// Mitsubishi GX Works2 project: DEMO_CCLv2-GATEWAY-V6ENET   PLC: L26-BT
// Demo V6 comm with CC-Link through HMS gateway

PROGRAM MAIN
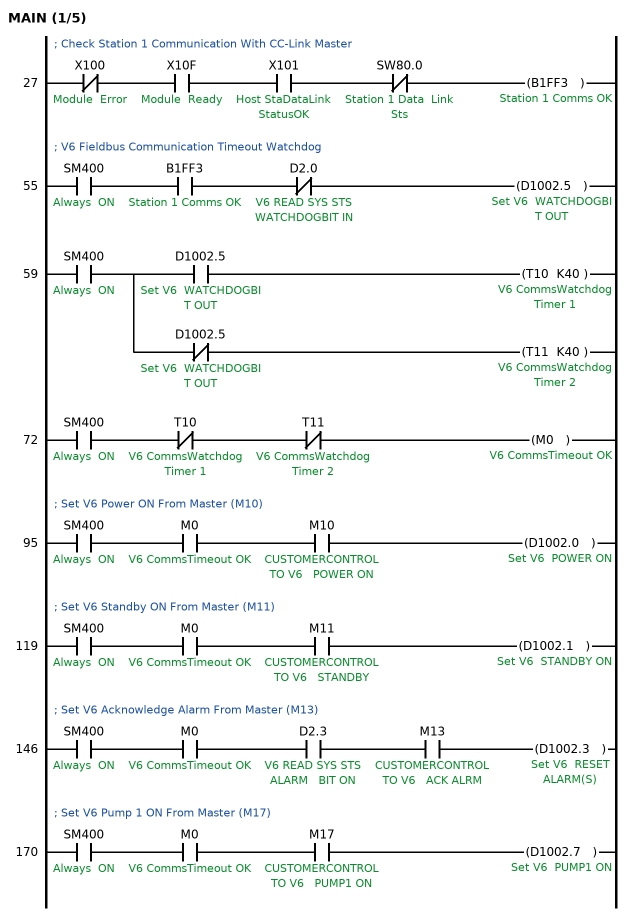
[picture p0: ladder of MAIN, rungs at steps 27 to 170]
; Check Station 1 Communication With CC-Link Master
27    LDI     X100  ; Module  Error
      AND     X10F  ; Module  Ready
      AND     X101  ; Host StaDataLinkStatusOK
      ANI     SW80.0  ; Station 1 Data  Link Sts
      OUT     B1FF3  ; Station 1 Comms OK
; V6 Fieldbus Communication Timeout Watchdog
55    LD      SM400  ; Always  ON
      AND     B1FF3  ; Station 1 Comms OK
      ANI     D2.0  ; V6 READ SYS STS WATCHDOGBIT IN
      OUT     D1002.5  ; Set V6  WATCHDOGBIT OUT
59    LD      SM400  ; Always  ON
      MPS
      AND     D1002.5  ; Set V6  WATCHDOGBIT OUT
      OUT     T10 K40  ; V6 CommsWatchdogTimer 1
      MPP
      ANI     D1002.5  ; Set V6  WATCHDOGBIT OUT
      OUT     T11 K40  ; V6 CommsWatchdogTimer 2
72    LD      SM400  ; Always  ON
      ANI     T10  ; V6 CommsWatchdogTimer 1
      ANI     T11  ; V6 CommsWatchdogTimer 2
      OUT     M0  ; V6 CommsTimeout OK
; Set V6 Power ON From Master (M10)
95    LD      SM400  ; Always  ON
      AND     M0  ; V6 CommsTimeout OK
      AND     M10  ; CUSTOMERCONTROL TO V6   POWER ON
      OUT     D1002.0  ; Set V6  POWER ON
; Set V6 Standby ON From Master (M11)
119   LD      SM400  ; Always  ON
      AND     M0  ; V6 CommsTimeout OK
      AND     M11  ; CUSTOMERCONTROL TO V6   STANDBY
      OUT     D1002.1  ; Set V6  STANDBY ON
; Set V6 Acknowledge Alarm From Master (M13)
146   LD      SM400  ; Always  ON
      AND     M0  ; V6 CommsTimeout OK
      AND     D2.3  ; V6 READ SYS STS ALARM   BIT ON
      AND     M13  ; CUSTOMERCONTROL TO V6   ACK ALRM
      OUT     D1002.3  ; Set V6  RESET   ALARM(S)
; Set V6 Pump 1 ON From Master (M17)
170   LD      SM400  ; Always  ON
      AND     M0  ; V6 CommsTimeout OK
      AND     M17  ; CUSTOMERCONTROL TO V6   PUMP1 ON
      OUT     D1002.7  ; Set V6  PUMP1 ON
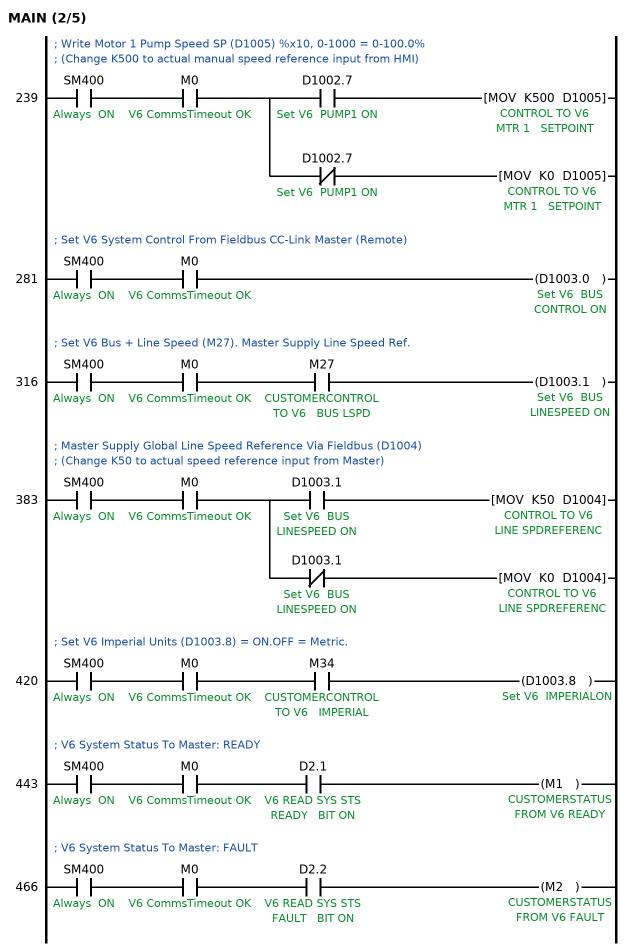
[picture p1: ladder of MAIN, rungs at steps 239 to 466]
; Write Motor 1 Pump Speed SP (D1005) %x10, 0-1000 = 0-100.0%
; (Change K500 to actual manual speed reference input from HMI)
239   LD      SM400  ; Always  ON
      AND     M0  ; V6 CommsTimeout OK
      MPS
      AND     D1002.7  ; Set V6  PUMP1 ON
      MOV     K500 D1005  ; CONTROL TO V6   MTR 1   SETPOINT
      MPP
      ANI     D1002.7  ; Set V6  PUMP1 ON
      MOV     K0 D1005
; Set V6 System Control From Fieldbus CC-Link Master (Remote)
281   LD      SM400  ; Always  ON
      AND     M0  ; V6 CommsTimeout OK
      OUT     D1003.0  ; Set V6  BUS     CONTROL ON
; Set V6 Bus + Line Speed (M27). Master Supply Line Speed Ref.
316   LD      SM400  ; Always  ON
      AND     M0  ; V6 CommsTimeout OK
      AND     M27  ; CUSTOMERCONTROL TO V6   BUS LSPD
      OUT     D1003.1  ; Set V6  BUS LINESPEED ON
; Master Supply Global Line Speed Reference Via Fieldbus (D1004)
; (Change K50 to actual speed reference input from Master)
383   LD      SM400  ; Always  ON
      AND     M0  ; V6 CommsTimeout OK
      MPS
      AND     D1003.1  ; Set V6  BUS LINESPEED ON
      MOV     K50 D1004  ; CONTROL TO V6   LINE SPDREFERENC
      MPP
      ANI     D1003.1  ; Set V6  BUS LINESPEED ON
      MOV     K0 D1004
; Set V6 Imperial Units (D1003.8) = ON.OFF = Metric.
420   LD      SM400  ; Always  ON
      AND     M0  ; V6 CommsTimeout OK
      AND     M34  ; CUSTOMERCONTROL TO V6   IMPERIAL
      OUT     D1003.8  ; Set V6  IMPERIALON
; V6 System Status To Master: READY
443   LD      SM400  ; Always  ON
      AND     M0  ; V6 CommsTimeout OK
      AND     D2.1  ; V6 READ SYS STS READY   BIT ON
      OUT     M1  ; CUSTOMERSTATUS  FROM V6 READY
; V6 System Status To Master: FAULT
466   LD      SM400  ; Always  ON
      AND     M0  ; V6 CommsTimeout OK
      AND     D2.2  ; V6 READ SYS STS FAULT   BIT ON
      OUT     M2  ; CUSTOMERSTATUS  FROM V6 FAULT
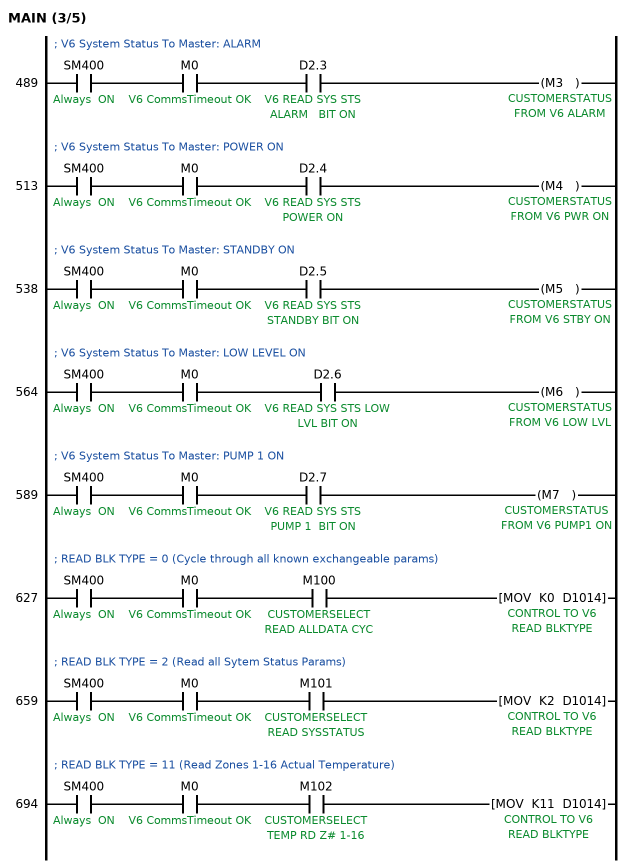
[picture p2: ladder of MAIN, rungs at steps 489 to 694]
; V6 System Status To Master: ALARM
489   LD      SM400  ; Always  ON
      AND     M0  ; V6 CommsTimeout OK
      AND     D2.3  ; V6 READ SYS STS ALARM   BIT ON
      OUT     M3  ; CUSTOMERSTATUS  FROM V6 ALARM
; V6 System Status To Master: POWER ON
513   LD      SM400  ; Always  ON
      AND     M0  ; V6 CommsTimeout OK
      AND     D2.4  ; V6 READ SYS STS POWER ON
      OUT     M4  ; CUSTOMERSTATUS  FROM V6 PWR ON
; V6 System Status To Master: STANDBY ON
538   LD      SM400  ; Always  ON
      AND     M0  ; V6 CommsTimeout OK
      AND     D2.5  ; V6 READ SYS STS STANDBY BIT ON
      OUT     M5  ; CUSTOMERSTATUS  FROM V6 STBY ON
; V6 System Status To Master: LOW LEVEL ON
564   LD      SM400  ; Always  ON
      AND     M0  ; V6 CommsTimeout OK
      AND     D2.6  ; V6 READ SYS STS LOW LVL BIT ON
      OUT     M6  ; CUSTOMERSTATUS  FROM V6 LOW LVL
; V6 System Status To Master: PUMP 1 ON
589   LD      SM400  ; Always  ON
      AND     M0  ; V6 CommsTimeout OK
      AND     D2.7  ; V6 READ SYS STS PUMP 1  BIT ON
      OUT     M7  ; CUSTOMERSTATUS  FROM V6 PUMP1 ON
; READ BLK TYPE = 0 (Cycle through all known exchangeable params)
627   LD      SM400  ; Always  ON
      AND     M0  ; V6 CommsTimeout OK
      AND     M100  ; CUSTOMERSELECT  READ ALLDATA CYC
      MOV     K0 D1014  ; CONTROL TO V6   READ BLKTYPE
; READ BLK TYPE = 2 (Read all Sytem Status Params)
659   LD      SM400  ; Always  ON
      AND     M0  ; V6 CommsTimeout OK
      AND     M101  ; CUSTOMERSELECT  READ SYSSTATUS
      MOV     K2 D1014
; READ BLK TYPE = 11 (Read Zones 1-16 Actual Temperature)
694   LD      SM400  ; Always  ON
      AND     M0  ; V6 CommsTimeout OK
      AND     M102  ; CUSTOMERSELECT  TEMP RD Z# 1-16
      MOV     K11 D1014
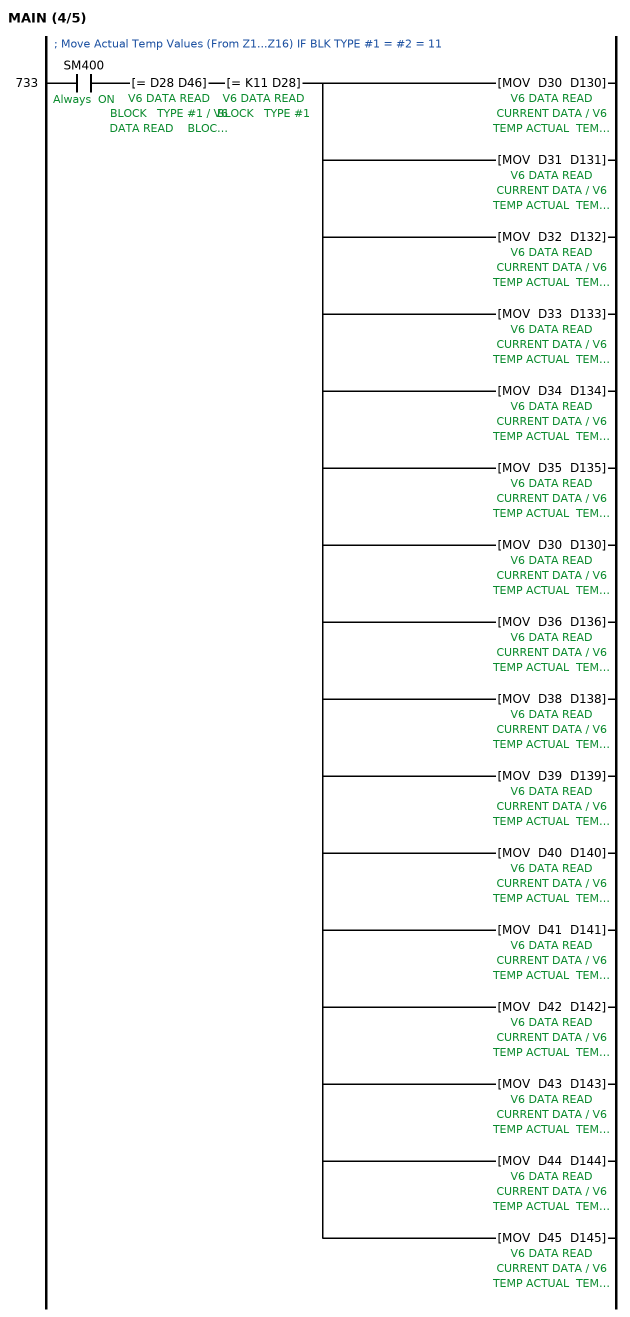
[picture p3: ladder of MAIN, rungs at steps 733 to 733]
; Move Actual Temp Values (From Z1...Z16) IF BLK TYPE #1 = #2 = 11
733   LD      SM400  ; Always  ON
      AND=    D28 D46  ; V6 DATA READ    BLOCK   TYPE #1 / V6 DATA READ    BLOCK   TYPE #2
      AND=    K11 D28  ; V6 DATA READ    BLOCK   TYPE #1
      MOV     D30 D130  ; V6 DATA READ    CURRENT DATA / V6 TEMP ACTUAL  TEMP    ZONE 1
      MOV     D31 D131  ; V6 DATA READ    CURRENT DATA / V6 TEMP ACTUAL  TEMP    ZONE 2
      MOV     D32 D132  ; V6 DATA READ    CURRENT DATA / V6 TEMP ACTUAL  TEMP    ZONE 3
      MOV     D33 D133  ; V6 DATA READ    CURRENT DATA / V6 TEMP ACTUAL  TEMP    ZONE 4
      MOV     D34 D134  ; V6 DATA READ    CURRENT DATA / V6 TEMP ACTUAL  TEMP    ZONE 5
      MOV     D35 D135  ; V6 DATA READ    CURRENT DATA / V6 TEMP ACTUAL  TEMP    ZONE 6
      MOV     D30 D130
      MOV     D36 D136  ; V6 DATA READ    CURRENT DATA / V6 TEMP ACTUAL  TEMP    ZONE 7
      MOV     D38 D138  ; V6 DATA READ    CURRENT DATA / V6 TEMP ACTUAL  TEMP    ZONE 9
      MOV     D39 D139  ; V6 DATA READ    CURRENT DATA / V6 TEMP ACTUAL  TEMP    ZONE 10
      MOV     D40 D140  ; V6 DATA READ    CURRENT DATA / V6 TEMP ACTUAL  TEMP    ZONE 11
      MOV     D41 D141  ; V6 DATA READ    CURRENT DATA / V6 TEMP ACTUAL  TEMP    ZONE 12
      MOV     D42 D142  ; V6 DATA READ    CURRENT DATA / V6 TEMP ACTUAL  TEMP    ZONE 13
      MOV     D43 D143  ; V6 DATA READ    CURRENT DATA / V6 TEMP ACTUAL  TEMP    ZONE 14
      MOV     D44 D144  ; V6 DATA READ    CURRENT DATA / V6 TEMP ACTUAL  TEMP    ZONE 15
      MOV     D45 D145  ; V6 DATA READ    CURRENT DATA / V6 TEMP ACTUAL  TEMP    ZONE 16
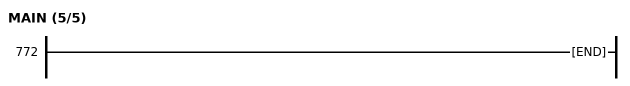
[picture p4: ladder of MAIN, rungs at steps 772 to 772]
772   END
END_PROGRAM

PROGRAM REGISTER
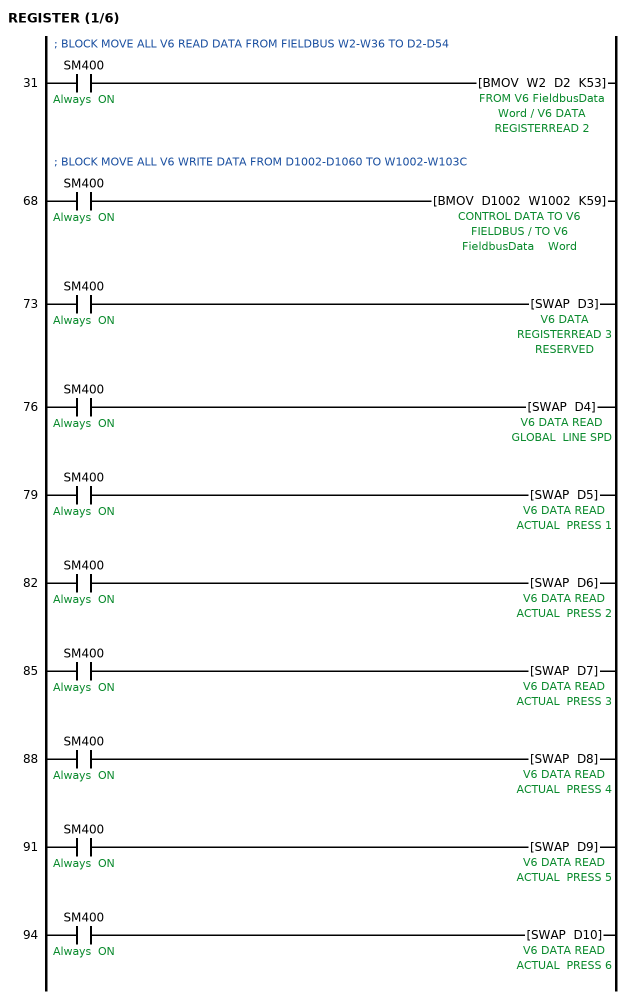
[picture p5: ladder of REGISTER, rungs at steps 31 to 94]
; BLOCK MOVE ALL V6 READ DATA FROM FIELDBUS W2-W36 TO D2-D54
31    LD      SM400  ; Always  ON
      BMOV    W2 D2 K53  ; FROM V6 FieldbusData    Word / V6 DATA REGISTERREAD 2
; BLOCK MOVE ALL V6 WRITE DATA FROM D1002-D1060 TO W1002-W103C
68    LD      SM400  ; Always  ON
      BMOV    D1002 W1002 K59  ; CONTROL DATA TO V6 FIELDBUS / TO V6   FieldbusData    Word
73    LD      SM400  ; Always  ON
      SWAP    D3  ; V6 DATA REGISTERREAD 3  RESERVED
76    LD      SM400  ; Always  ON
      SWAP    D4  ; V6 DATA READ    GLOBAL  LINE SPD
79    LD      SM400  ; Always  ON
      SWAP    D5  ; V6 DATA READ    ACTUAL  PRESS 1
82    LD      SM400  ; Always  ON
      SWAP    D6  ; V6 DATA READ    ACTUAL  PRESS 2
85    LD      SM400  ; Always  ON
      SWAP    D7  ; V6 DATA READ    ACTUAL  PRESS 3
88    LD      SM400  ; Always  ON
      SWAP    D8  ; V6 DATA READ    ACTUAL  PRESS 4
91    LD      SM400  ; Always  ON
      SWAP    D9  ; V6 DATA READ    ACTUAL  PRESS 5
94    LD      SM400  ; Always  ON
      SWAP    D10  ; V6 DATA READ    ACTUAL  PRESS 6
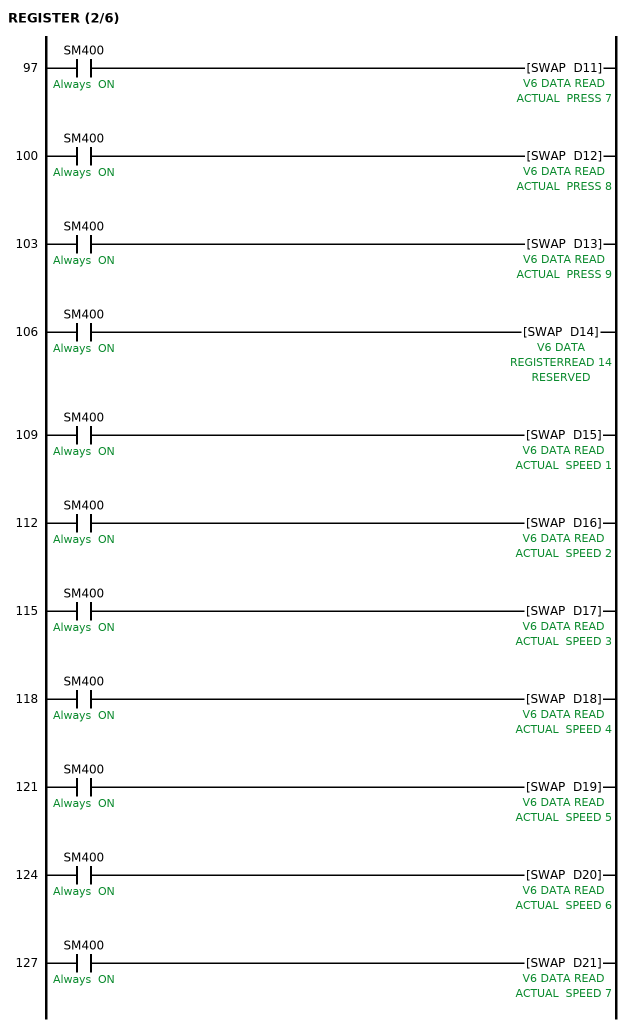
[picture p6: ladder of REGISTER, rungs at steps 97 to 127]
97    LD      SM400  ; Always  ON
      SWAP    D11  ; V6 DATA READ    ACTUAL  PRESS 7
100   LD      SM400  ; Always  ON
      SWAP    D12  ; V6 DATA READ    ACTUAL  PRESS 8
103   LD      SM400  ; Always  ON
      SWAP    D13  ; V6 DATA READ    ACTUAL  PRESS 9
106   LD      SM400  ; Always  ON
      SWAP    D14  ; V6 DATA REGISTERREAD 14 RESERVED
109   LD      SM400  ; Always  ON
      SWAP    D15  ; V6 DATA READ    ACTUAL  SPEED 1
112   LD      SM400  ; Always  ON
      SWAP    D16  ; V6 DATA READ    ACTUAL  SPEED 2
115   LD      SM400  ; Always  ON
      SWAP    D17  ; V6 DATA READ    ACTUAL  SPEED 3
118   LD      SM400  ; Always  ON
      SWAP    D18  ; V6 DATA READ    ACTUAL  SPEED 4
121   LD      SM400  ; Always  ON
      SWAP    D19  ; V6 DATA READ    ACTUAL  SPEED 5
124   LD      SM400  ; Always  ON
      SWAP    D20  ; V6 DATA READ    ACTUAL  SPEED 6
127   LD      SM400  ; Always  ON
      SWAP    D21  ; V6 DATA READ    ACTUAL  SPEED 7
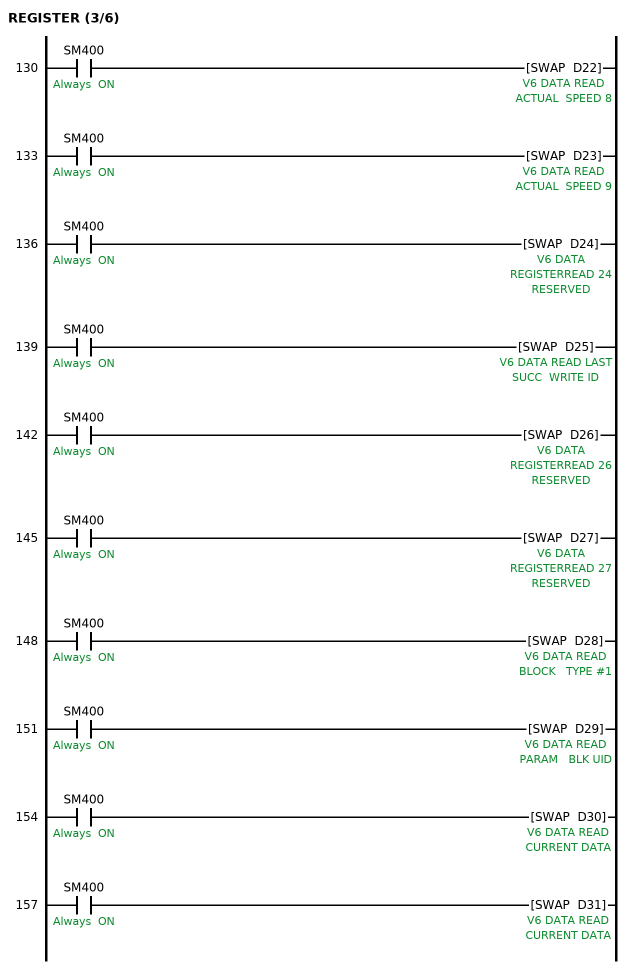
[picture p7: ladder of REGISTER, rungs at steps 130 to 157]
130   LD      SM400  ; Always  ON
      SWAP    D22  ; V6 DATA READ    ACTUAL  SPEED 8
133   LD      SM400  ; Always  ON
      SWAP    D23  ; V6 DATA READ    ACTUAL  SPEED 9
136   LD      SM400  ; Always  ON
      SWAP    D24  ; V6 DATA REGISTERREAD 24 RESERVED
139   LD      SM400  ; Always  ON
      SWAP    D25  ; V6 DATA READ LAST SUCC  WRITE ID
142   LD      SM400  ; Always  ON
      SWAP    D26  ; V6 DATA REGISTERREAD 26 RESERVED
145   LD      SM400  ; Always  ON
      SWAP    D27  ; V6 DATA REGISTERREAD 27 RESERVED
148   LD      SM400  ; Always  ON
      SWAP    D28  ; V6 DATA READ    BLOCK   TYPE #1
151   LD      SM400  ; Always  ON
      SWAP    D29  ; V6 DATA READ    PARAM   BLK UID
154   LD      SM400  ; Always  ON
      SWAP    D30  ; V6 DATA READ    CURRENT DATA
157   LD      SM400  ; Always  ON
      SWAP    D31  ; V6 DATA READ    CURRENT DATA
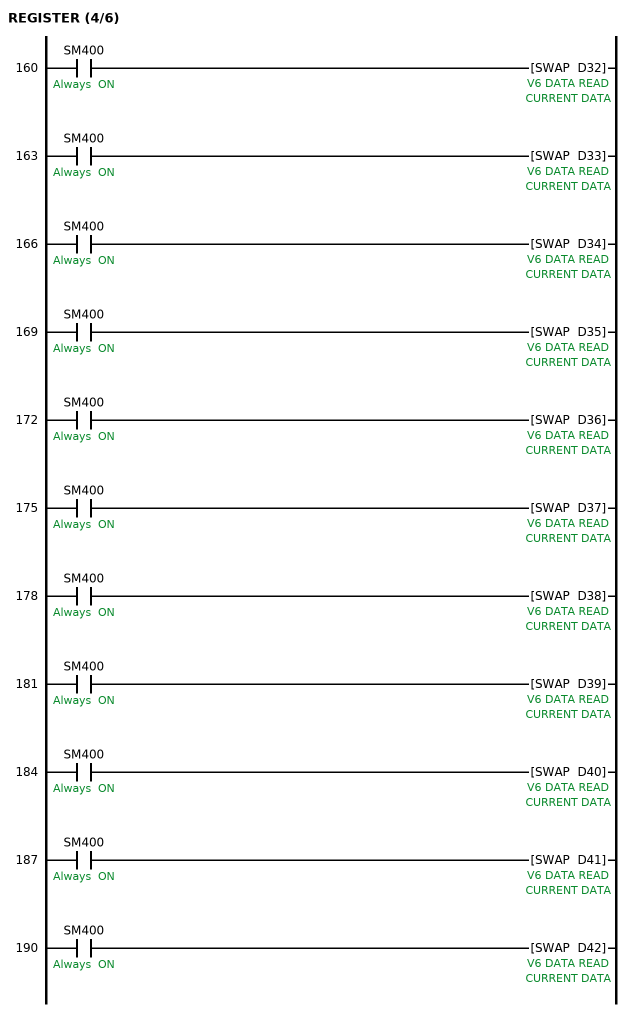
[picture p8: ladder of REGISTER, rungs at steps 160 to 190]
160   LD      SM400  ; Always  ON
      SWAP    D32  ; V6 DATA READ    CURRENT DATA
163   LD      SM400  ; Always  ON
      SWAP    D33  ; V6 DATA READ    CURRENT DATA
166   LD      SM400  ; Always  ON
      SWAP    D34  ; V6 DATA READ    CURRENT DATA
169   LD      SM400  ; Always  ON
      SWAP    D35  ; V6 DATA READ    CURRENT DATA
172   LD      SM400  ; Always  ON
      SWAP    D36  ; V6 DATA READ    CURRENT DATA
175   LD      SM400  ; Always  ON
      SWAP    D37  ; V6 DATA READ    CURRENT DATA
178   LD      SM400  ; Always  ON
      SWAP    D38  ; V6 DATA READ    CURRENT DATA
181   LD      SM400  ; Always  ON
      SWAP    D39  ; V6 DATA READ    CURRENT DATA
184   LD      SM400  ; Always  ON
      SWAP    D40  ; V6 DATA READ    CURRENT DATA
187   LD      SM400  ; Always  ON
      SWAP    D41  ; V6 DATA READ    CURRENT DATA
190   LD      SM400  ; Always  ON
      SWAP    D42  ; V6 DATA READ    CURRENT DATA
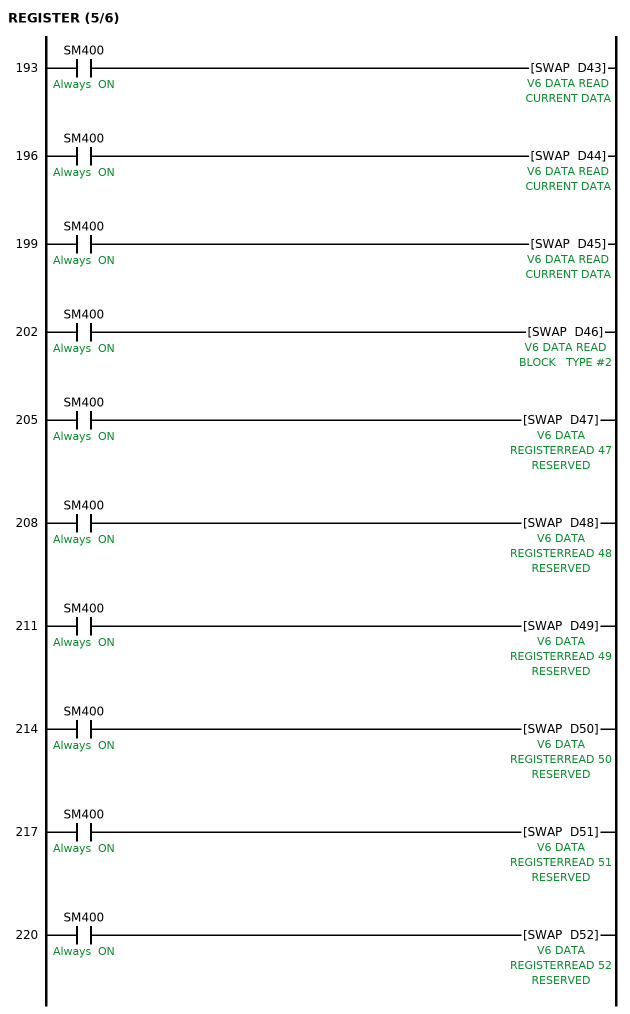
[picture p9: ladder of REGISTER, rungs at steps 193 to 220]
193   LD      SM400  ; Always  ON
      SWAP    D43  ; V6 DATA READ    CURRENT DATA
196   LD      SM400  ; Always  ON
      SWAP    D44  ; V6 DATA READ    CURRENT DATA
199   LD      SM400  ; Always  ON
      SWAP    D45  ; V6 DATA READ    CURRENT DATA
202   LD      SM400  ; Always  ON
      SWAP    D46  ; V6 DATA READ    BLOCK   TYPE #2
205   LD      SM400  ; Always  ON
      SWAP    D47  ; V6 DATA REGISTERREAD 47 RESERVED
208   LD      SM400  ; Always  ON
      SWAP    D48  ; V6 DATA REGISTERREAD 48 RESERVED
211   LD      SM400  ; Always  ON
      SWAP    D49  ; V6 DATA REGISTERREAD 49 RESERVED
214   LD      SM400  ; Always  ON
      SWAP    D50  ; V6 DATA REGISTERREAD 50 RESERVED
217   LD      SM400  ; Always  ON
      SWAP    D51  ; V6 DATA REGISTERREAD 51 RESERVED
220   LD      SM400  ; Always  ON
      SWAP    D52  ; V6 DATA REGISTERREAD 52 RESERVED
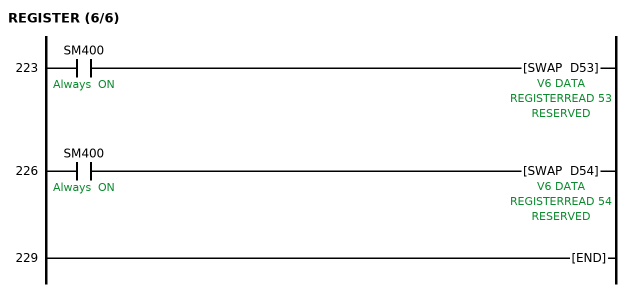
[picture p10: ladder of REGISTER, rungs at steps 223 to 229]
223   LD      SM400  ; Always  ON
      SWAP    D53  ; V6 DATA REGISTERREAD 53 RESERVED
226   LD      SM400  ; Always  ON
      SWAP    D54  ; V6 DATA REGISTERREAD 54 RESERVED
229   END
END_PROGRAM

// device comments not shown above
W36  ; FROM V6 FieldbusDataWordRESERVED
W103C  ; TO V6   FieldbusDataWordRESERVED
D1060  ; V6 DATA RESERVEDWORD
W4  ; FROM V6 FieldbusData GBLLINESPD
W5  ; FROM V6 FieldbusData ACTPRESS 1
W6  ; FROM V6 FieldbusData ACTPRESS 2
W7  ; FROM V6 FieldbusData ACTPRESS 3
W8  ; FROM V6 FieldbusData ACTPRESS 4
W9  ; FROM V6 FieldbusData ACTPRESS 5
W0A  ; FROM V6 FieldbusData ACTPRESS 6
W0B  ; FROM V6 FieldbusData ACTPRESS 7
W0C  ; FROM V6 FieldbusData ACTPRESS 8
W0D  ; FROM V6 FieldbusData ACTPRESS 9
W0F  ; FROM V6 FieldbusData ACTSPEED 1
W10  ; FROM V6 FieldbusData ACTSPEED 2
W11  ; FROM V6 FieldbusData ACTSPEED 3
W12  ; FROM V6 FieldbusData ACTSPEED 4
W13  ; FROM V6 FieldbusData ACTSPEED 5
W14  ; FROM V6 FieldbusData ACTSPEED 6
W15  ; FROM V6 FieldbusData ACTSPEED 7
W16  ; FROM V6 FieldbusData ACTSPEED 8
W17  ; FROM V6 FieldbusData ACTSPEED 9
W19  ; FROM V6 FieldbusLAST SUCWRITE ID
W1C  ; FROM V6 FieldbusREAD BLKTYPE #1
W1D  ; FROM V6 FieldbusREAD PARBLK UID
W2E  ; FROM V6 FieldbusREAD BLKTYPE #2
W1003  ; TO V6   FieldbusData    Word
W1004  ; TO V6   FieldbusGLOBAL  LINE SPD
W1005  ; TO V6   FieldbusMOTOR 1 SETPOINT
W1006  ; TO V6   FieldbusMOTOR 2 SETPOINT
W1007  ; TO V6   FieldbusMOTOR 3 SETPOINT
W1008  ; TO V6   FieldbusMOTOR 4 SETPOINT
W1009  ; TO V6   FieldbusMOTOR 5 SETPOINT
W100A  ; TO V6   FieldbusMOTOR 6 SETPOINT
W100B  ; TO V6   FieldbusMOTOR 7 SETPOINT
W100C  ; TO V6   FieldbusMOTOR 8 SETPOINT
W100D  ; TO V6   FieldbusMOTOR 9 SETPOINT
W100E  ; TO V6   FieldbusRD BLK  TYPE
W100F  ; TO V6   FieldbusRD BLK  UID
W1012  ; TO V6   FieldbusWR BLK  TYPE #1
W1013  ; TO V6   FieldbusWR BLK  UID
W1026  ; TO V6   FieldbusWR BLK  TYPE #2
M18  ; CUSTOMERCONTROL TO V6   PUMP2 ON
M19  ; CUSTOMERCONTROL TO V6   PUMP3 ON
M20  ; CUSTOMERCONTROL TO V6   PUMP4 ON
M21  ; CUSTOMERCONTROL TO V6   PUMP5 ON
M22  ; CUSTOMERCONTROL TO V6   PUMP6 ON
M23  ; CUSTOMERCONTROL TO V6   PUMP7 ON
M24  ; CUSTOMERCONTROL TO V6   PUMP8 ON
M25  ; CUSTOMERCONTROL TO V6   PUMP9 ON
M26  ; CUSTOMERCONTROL TO V6   BUS CTRL
M103  ; CUSTOMERSELECT  TEMP RD Z# 17-32
M104  ; CUSTOMERSELECT  TEMP RD Z# 33-48
M105  ; CUSTOMERSELECT  TEMP RD Z# 49-64
M106  ; CUSTOMERSELECT  TEMP RD SP#1-16
M107  ; CUSTOMERSELECT  TEMP RD SP#17-32
M108  ; CUSTOMERSELECT  TEMP RD SP#33-48
M109  ; CUSTOMERSELECT  TEMP RD SP#49-64
M110  ; CUSTOMERSELECT  TEMP RD STS 1-16
M111  ; CUSTOMERSELECT  TEMP RD STS17-32
M112  ; CUSTOMERSELECT  TEMP RD STS33-48
M113  ; CUSTOMERSELECT  TEMP RD STS49-64
D0  ; V6 DATA REGISTERREAD 0  RESERVED
D1  ; V6 DATA REGISTERREAD 1  RESERVED
D137  ; V6 TEMP ACTUAL  TEMP    ZONE 8
D146  ; V6 TEMP ACTUAL  TEMP    ZONE 17
D147  ; V6 TEMP ACTUAL  TEMP    ZONE 18
D148  ; V6 TEMP ACTUAL  TEMP    ZONE 19
D149  ; V6 TEMP ACTUAL  TEMP    ZONE 20
D150  ; V6 TEMP ACTUAL  TEMP    ZONE 21
D151  ; V6 TEMP ACTUAL  TEMP    ZONE 22
D152  ; V6 TEMP ACTUAL  TEMP    ZONE 23
D153  ; V6 TEMP ACTUAL  TEMP    ZONE 24
D154  ; V6 TEMP ACTUAL  TEMP    ZONE 25
D155  ; V6 TEMP ACTUAL  TEMP    ZONE 26
D156  ; V6 TEMP ACTUAL  TEMP    ZONE 27
D157  ; V6 TEMP ACTUAL  TEMP    ZONE 28
D158  ; V6 TEMP ACTUAL  TEMP    ZONE 29
D159  ; V6 TEMP ACTUAL  TEMP    ZONE 30
D160  ; V6 TEMP ACTUAL  TEMP    ZONE 31
D161  ; V6 TEMP ACTUAL  TEMP    ZONE 32
D162  ; V6 TEMP ACTUAL  TEMP    ZONE 33
D163  ; V6 TEMP ACTUAL  TEMP    ZONE 34
D164  ; V6 TEMP ACTUAL  TEMP    ZONE 35
D165  ; V6 TEMP ACTUAL  TEMP    ZONE 36
D166  ; V6 TEMP ACTUAL  TEMP    ZONE 37
D167  ; V6 TEMP ACTUAL  TEMP    ZONE 38
D168  ; V6 TEMP ACTUAL  TEMP    ZONE 39
D169  ; V6 TEMP ACTUAL  TEMP    ZONE 40
D170  ; V6 TEMP ACTUAL  TEMP    ZONE 41
D171  ; V6 TEMP ACTUAL  TEMP    ZONE 42
D172  ; V6 TEMP ACTUAL  TEMP    ZONE 43
D173  ; V6 TEMP ACTUAL  TEMP    ZONE 44
D174  ; V6 TEMP ACTUAL  TEMP    ZONE 45
D175  ; V6 TEMP ACTUAL  TEMP    ZONE 46
D176  ; V6 TEMP ACTUAL  TEMP    ZONE 47
D177  ; V6 TEMP ACTUAL  TEMP    ZONE 48
D178  ; V6 TEMP ACTUAL  TEMP    ZONE 49
D179  ; V6 TEMP ACTUAL  TEMP    ZONE 50
D180  ; V6 TEMP ACTUAL  TEMP    ZONE 51
D181  ; V6 TEMP ACTUAL  TEMP    ZONE 52
D182  ; V6 TEMP ACTUAL  TEMP    ZONE 53
D183  ; V6 TEMP ACTUAL  TEMP    ZONE 54
D184  ; V6 TEMP ACTUAL  TEMP    ZONE 55
D185  ; V6 TEMP ACTUAL  TEMP    ZONE 56
D186  ; V6 TEMP ACTUAL  TEMP    ZONE 57
D187  ; V6 TEMP ACTUAL  TEMP    ZONE 58
D188  ; V6 TEMP ACTUAL  TEMP    ZONE 59
D189  ; V6 TEMP ACTUAL  TEMP    ZONE 60
D190  ; V6 TEMP ACTUAL  TEMP    ZONE 61
D191  ; V6 TEMP ACTUAL  TEMP    ZONE 62
D192  ; V6 TEMP ACTUAL  TEMP    ZONE 63
D193  ; V6 TEMP ACTUAL  TEMP    ZONE 64
D1000  ; Not Used
D1001  ; Not Used
D1003  ; CONTROL DATA TO V6 FIELDBUS
D1006  ; CONTROL TO V6   MTR 2   SETPOINT
D1007  ; CONTROL TO V6   MTR 3   SETPOINT
D1008  ; CONTROL TO V6   MTR 4   SETPOINT
D1009  ; CONTROL TO V6   MTR 5   SETPOINT
D1010  ; CONTROL TO V6   MTR 6   SETPOINT
D1011  ; CONTROL TO V6   MTR 7   SETPOINT
D1012  ; CONTROL TO V6   MTR 8   SETPOINT
D1013  ; CONTROL TO V6   MTR 9   SETPOINT
D1015  ; CONTROL TO V6   READ BLKUID
D1018  ; CONTROL TO V6   WR BLK  TYPE #1
D1019  ; CONTROL TO V6   WR BLK  UID
D1022  ; CONTROL TO V6   CURRENT DATA 1
D1023  ; CONTROL TO V6   CURRENT DATA 2
D1024  ; CONTROL TO V6   CURRENT DATA 3
D1025  ; CONTROL TO V6   CURRENT DATA 4
D1026  ; CONTROL TO V6   CURRENT DATA 5
D1027  ; CONTROL TO V6   CURRENT DATA 6
D1028  ; CONTROL TO V6   CURRENT DATA 7
D1029  ; CONTROL TO V6   CURRENT DATA 8
D1030  ; CONTROL TO V6   CURRENT DATA 9
D1031  ; CONTROL TO V6   CURRENT DATA 10
D1032  ; CONTROL TO V6   CURRENT DATA 11
D1033  ; CONTROL TO V6   CURRENT DATA 12
D1034  ; CONTROL TO V6   CURRENT DATA 13
D1035  ; CONTROL TO V6   CURRENT DATA 14
D1036  ; CONTROL TO V6   CURRENT DATA 15
D1037  ; CONTROL TO V6   CURRENT DATA 16
D1038  ; CONTROL TO V6   WR BLK  TYPE #2
D2.8  ; V6 READ SYS STS PUMP 2  BIT ON
D2.9  ; V6 READ SYS STS PUMP 3  BIT ON
D2.A  ; V6 READ SYS STS PUMP 4  BIT ON
D2.B  ; V6 READ SYS STS PUMP 5  BIT ON
D2.C  ; V6 READ SYS STS PUMP 6  BIT ON
D2.D  ; V6 READ SYS STS PUMP 7  BIT ON
D2.E  ; V6 READ SYS STS PUMP 8  BIT ON
D2.F  ; V6 READ SYS STS PUMP 9  BIT ON
D1002.8  ; Set V6  PUMP2 ON
D1002.9  ; Set V6  PUMP3 ON
D1002.A  ; Set V6  PUMP4 ON
D1002.B  ; Set V6  PUMP5 ON
D1002.C  ; Set V6  PUMP6 ON
D1002.D  ; Set V6  PUMP7 ON
D1002.E  ; Set V6  PUMP8 ON
D1002.F  ; Set V6  PUMP9 ON
W2.0  ; FROM V6 FieldbusSys StatWATCHDOG
W2.1  ; FROM V6 FieldbusSys Sts READY
W2.2  ; FROM V6 FieldbusSys Sts FAULT
W2.3  ; FROM V6 FieldbusSys Sts ALARM
W2.4  ; FROM V6 FieldbusSys Sts PWR ON
W2.5  ; FROM V6 FieldbusSys Sts STBY ON
W2.6  ; FROM V6 FieldbusSys Sts LOW LVL
W2.7  ; FROM V6 FieldbusSys Sts PUMP1 ON
W2.8  ; FROM V6 FieldbusSys Sts PUMP2 ON
W2.9  ; FROM V6 FieldbusSys Sts PUMP3 ON
W2.A  ; FROM V6 FieldbusSys Sts PUMP4 ON
W2.B  ; FROM V6 FieldbusSys Sts PUMP5 ON
W2.C  ; FROM V6 FieldbusSys Sts PUMP6 ON
W2.D  ; FROM V6 FieldbusSys Sts PUMP7 ON
W2.E  ; FROM V6 FieldbusSys Sts PUMP8 ON
W2.F  ; FROM V6 FieldbusSys Sts PUMP9 ON
W102.0  ; FROM V6 FieldbusWatchdogBit In
W1002.0  ; TO V6   FieldbusSys Set POWER ON
W1002.1  ; TO V6   FieldbusSys Set STANDBY
W1002.3  ; TO V6   FieldbusSys Set ACK ALRM
W1002.5  ; TO V6   FieldbusSys Set WATCHDOG
W1002.7  ; TO V6   FieldbusSys Set PUMP1 ON
W1002.8  ; TO V6   FieldbusSys Set PUMP2 ON
W1002.9  ; TO V6   FieldbusSys Set PUMP3 ON
W1002.A  ; TO V6   FieldbusSys Set PUMP4 ON
W1002.B  ; TO V6   FieldbusSys Set PUMP5 ON
W1002.C  ; TO V6   FieldbusSys Set PUMP6 ON
W1002.D  ; TO V6   FieldbusSys Set PUMP7 ON
W1002.E  ; TO V6   FieldbusSys Set PUMP8 ON
W1002.F  ; TO V6   FieldbusSys Set PUMP9 ON
W1003.0  ; TO V6   FieldbusSys CtrlBUS CTRL
W1003.1  ; TO V6   FieldbusSys CtrlBUS LSPD
W1003.8  ; TO V6   FieldbusSys CtrlIMPERIAL
